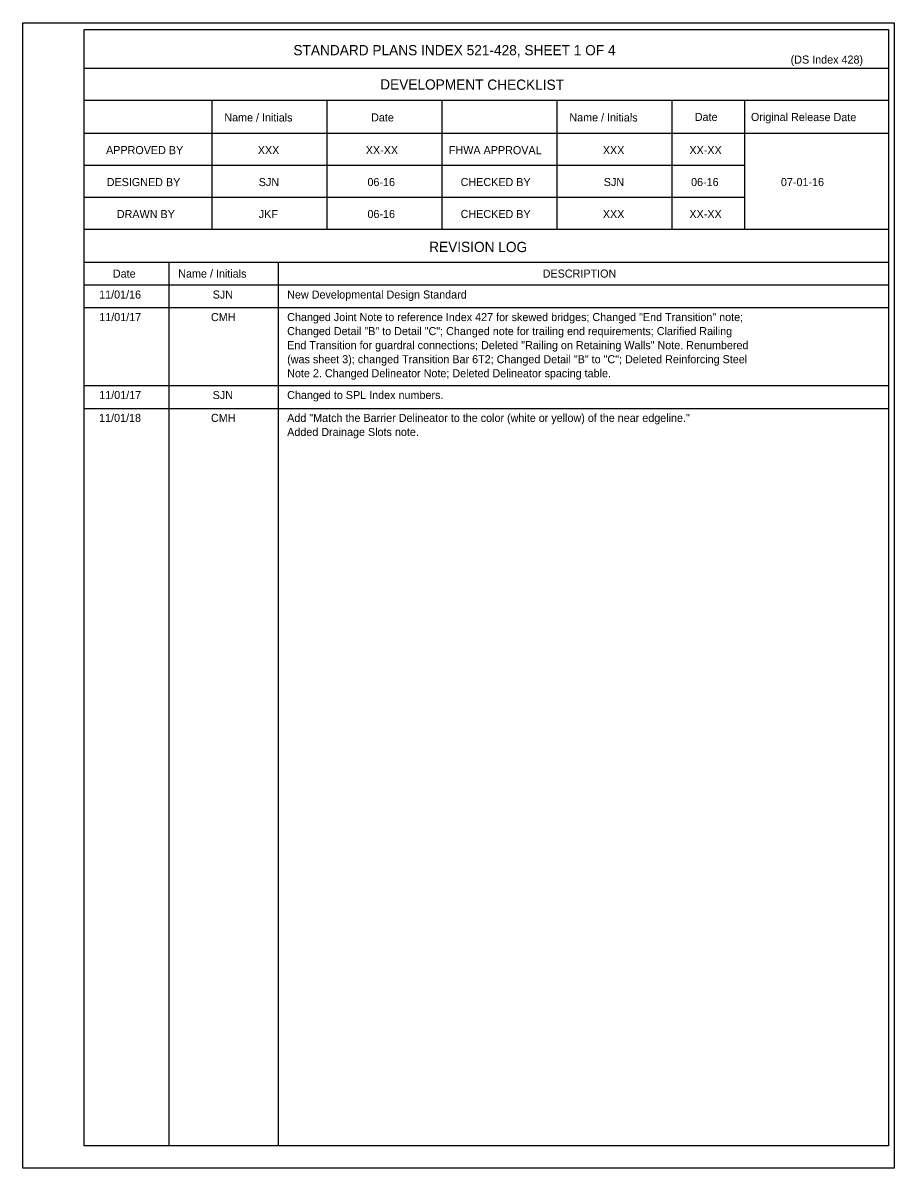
# Model space of a CAD drawing. Extents: x 130649.2 to 130733.9, y 88659.3 to 88705.5.
# Drawn here: x 130712.11 to 130733.92, y 88673.48 to 88702.14 of the extents above; entities that cross this region are included whole.
import ezdxf

# ---------------------------------------------------------------- set-up
doc = ezdxf.new("R2010")
doc.units = 0
for name, color, linetype in [('Border', 7, 'Continuous'), ('Patterning', 7, 'Continuous'), ('PlotBorder_dp', 7, 'Continuous'), ('SheetBorder_dp', 7, 'Continuous')]:
    doc.layers.add(name, color=color, linetype=linetype)

msp = doc.modelspace()

# ---------------------------------------------------------------- linework, layer by layer
at = {"layer": 'Border'}
for p, q in [((130733.782, 88700.999), (130713.636, 88700.999)), ((130733.782, 88700.199), (130713.636, 88700.199)), ((130716.836, 88700.199), (130716.836, 88696.972)), ((130719.716, 88700.199), (130719.716, 88696.972)), ((130722.596, 88700.199), (130722.596, 88696.972)), ((130725.476, 88700.199), (130725.476, 88696.972)), ((130728.356, 88700.199), (130728.356, 88696.972)), ((130730.17, 88700.199), (130730.17, 88696.972)), ((130733.782, 88699.372), (130713.636, 88699.372)), ((130730.17, 88698.572), (130713.636, 88698.572)), ((130730.17, 88697.772), (130713.636, 88697.772)), ((130733.782, 88696.972), (130713.636, 88696.972)), ((130733.782, 88696.144), (130713.636, 88696.144)), ((130715.756, 88696.144), (130715.756, 88674.037)), ((130718.498, 88696.144), (130718.498, 88674.037)), ((130733.782, 88695.58), (130713.636, 88695.58))]:
    msp.add_line(p, q, dxfattribs=at)
msp.add_lwpolyline([(130713.636, 88701.98), (130733.782, 88701.98), (130733.782, 88674.037), (130713.636, 88674.037)], close=True, dxfattribs=at)
at = {"layer": 'PlotBorder_dp'}
for p, q in [((130713.636, 88695.016), (130733.782, 88695.016)), ((130713.636, 88693.065), (130733.782, 88693.065)), ((130713.636, 88692.492), (130733.782, 88692.492))]:
    msp.add_line(p, q, dxfattribs=at)
at = {"layer": 'SheetBorder_dp'}
msp.add_line((130712.105, 88673.476), (130712.105, 88673.476), dxfattribs=at)
msp.add_lwpolyline([(130712.105, 88702.143), (130733.918, 88702.143), (130733.918, 88673.476), (130712.105, 88673.476)], close=True, dxfattribs=at)

# ---------------------------------------------------------------- texts
at = {"layer": 'Patterning'}
for s, height, p in [('STANDARD PLANS INDEX 521-428, SHEET 1 OF 4', 0.256, (130718.878, 88701.332)), ('XXX', 0.2016, (130717.986, 88698.858)), ('XX-XX', 0.2016, (130720.69, 88698.858)), ('XXX', 0.2016, (130726.626, 88698.858)), ('XX-XX', 0.2016, (130728.793, 88698.858)), ('SJN', 0.2016, (130718.01, 88698.058)), ('06-16', 0.2016, (130720.732, 88698.058)), ('SJN', 0.2016, (130726.65, 88698.058)), ('06-16', 0.2016, (130728.835, 88698.058)), ('07-01-16', 0.2016, (130731.085, 88698.058)), ('JKF', 0.2016, (130718.012, 88697.258)), ('06-16', 0.2016, (130720.732, 88697.258)), ('XXX', 0.2016, (130726.626, 88697.258)), ('XX-XX', 0.2016, (130728.793, 88697.258)), ('DESCRIPTION', 0.2016, (130725.119, 88695.767)), ('11/01/16', 0.2016, (130714.014, 88695.242)), ('SJN', 0.2016, (130716.857, 88695.242)), ('New Developmental Design Standard', 0.2016, (130718.722, 88695.242)), ('11/01/17', 0.2016, (130714.017, 88694.678)), ('CMH', 0.2016, (130716.814, 88694.678)), ('Changed Joint Note to reference Index 427 for skewed bridges; Changed "End Transition" note;', 0.2016, (130718.722, 88694.678)), ('Changed Detail "B" to Detail "C"; Changed note for trailing end requirements; Clarified Railing', 0.2016, (130718.722, 88694.327)), ('End Transition for guardral connections; Deleted "Railing on Retaining Walls" Note. Renumbered', 0.2016, (130718.722, 88693.975)), ('(was sheet 3); changed Transition Bar 6T2; Changed Detail "B" to "C"; Deleted Reinforcing Steel', 0.2016, (130718.722, 88693.623)), ('Note 2. Changed Delineator Note; Deleted Delineator spacing table.', 0.2016, (130718.722, 88693.272)), ('11/01/17', 0.2016, (130714.017, 88692.727)), ('SJN', 0.2016, (130716.857, 88692.727)), ('Changed to SPL Index numbers.', 0.2016, (130718.722, 88692.727)), ('11/01/18', 0.2016, (130714.013, 88692.154)), ('CMH', 0.2016, (130716.814, 88692.154)), ('Add "Match the Barrier Delineator to the color (white or yellow) of the near edgeline."', 0.2016, (130718.722, 88692.154)), ('Added Drainage Slots note.', 0.2016, (130718.722, 88691.802))]:
    msp.add_text(s, height=height, dxfattribs=at).set_placement(p)
for s, height, p in [('DEVELOPMENT CHECKLIST', 0.256, (130721.051, 88700.476)), ('Name / Initials', 0.2016, (130717.148, 88699.678)), ('Date', 0.2016, (130720.823, 88699.677)), ('Name / Initials', 0.2016, (130725.788, 88699.678)), ('Date', 0.2016, (130728.928, 88699.688)), ('Original Release Date', 0.2016, (130730.334, 88699.688)), ('APPROVED BY', 0.2016, (130714.187, 88698.86)), ('FHWA APPROVAL', 0.2016, (130722.771, 88698.86)), ('DESIGNED BY', 0.2016, (130714.204, 88698.059)), ('CHECKED BY', 0.2016, (130723.065, 88698.06)), ('DRAWN BY', 0.2016, (130714.457, 88697.258)), ('CHECKED BY', 0.2016, (130723.065, 88697.26)), ('REVISION LOG', 0.256, (130722.277, 88696.41)), ('Date', 0.2016, (130714.358, 88695.767)), ('Name / Initials', 0.2016, (130715.994, 88695.769))]:
    msp.add_text(s, height=height, rotation=359.8756, dxfattribs=at).set_placement(p)
at = {"layer": 'PlotBorder_dp'}
msp.add_text('(DS Index 428)', height=0.2016, dxfattribs=at).set_placement((130731.328, 88701.124))

doc.saveas('drawing.dxf')
